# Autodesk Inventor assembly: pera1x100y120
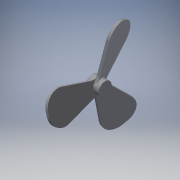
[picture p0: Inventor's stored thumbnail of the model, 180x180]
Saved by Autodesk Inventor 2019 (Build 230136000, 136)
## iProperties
Created: 2020-08
Part Number: pera1x100y120
Material: 一般
Document SubType Name: Assembly
Designer: kikut
Author: kikut
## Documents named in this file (2)
- F:\openFOAM\bathrobo\bathrobo01\oversetmeshpera1\CAD\pera1x100y120.iam
- F:\openFOAM\bathrobo\bathrobo01\oversetmeshpera1\CAD\pera01.ipt
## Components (1 placed, 1 different names)
1. pera01:1 — メイト:1, メイト:2
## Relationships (2: Mate 2)
- メイト:1 [Mate]: pera01:1
- メイト:2 [Mate]: pera01:1
